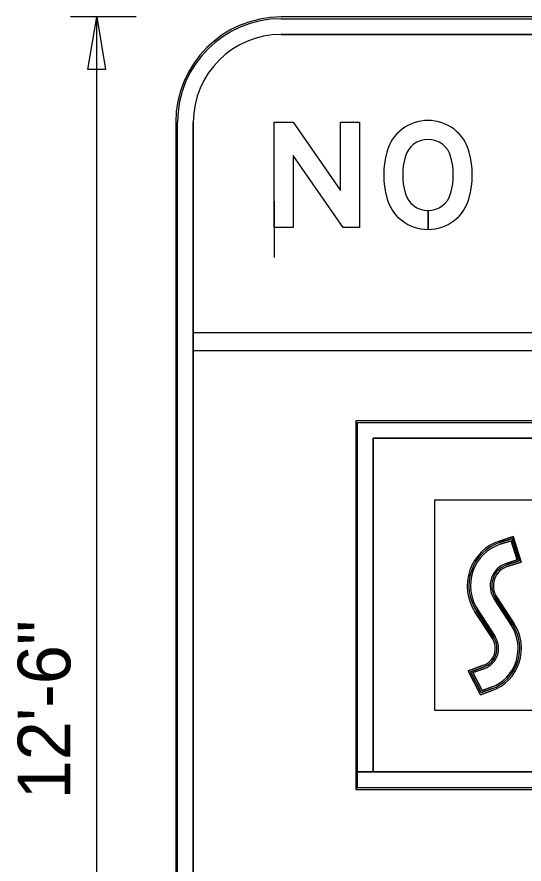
# Model space of a CAD drawing. Extents: x 119523 to 121850, y -23542 to -19972.
# Drawn here: x 121310.8 to 121368.6, y -22914.3 to -22817.8 of the extents above; entities that cross this region are included whole.
import ezdxf

# ---------------------------------------------------------------- set-up
doc = ezdxf.new("R2010")
doc.units = 0
for name, color, linetype in [('GSBWFill', 7, 'Continuous'), ('GSColorFill', 7, 'Continuous'), ('GSDims', 7, 'Continuous'), ('GSOutline', 7, 'Continuous')]:
    doc.layers.add(name, color=color, linetype=linetype)

msp = doc.modelspace()

# ---------------------------------------------------------------- linework, layer by layer
at = {"layer": 'GSBWFill'}
for p, q in [((121442.9, -22817.831), (121340.9, -22817.831)), ((121340.9, -22819.831), (121442.9, -22819.831)), ((121328.9, -22829.831), (121328.9, -22955.831)), ((121330.9, -22955.831), (121330.9, -22829.831)), ((121357.64, -22839.881), (121357.64, -22842.041)), ((121357.641, -22842.041), (121357.641, -22839.881)), ((121452.9, -22853.831), (121330.9, -22853.831)), ((121330.9, -22853.831), (121330.9, -22855.831)), ((121330.9, -22855.831), (121452.9, -22855.831)), ((121434.4, -22863.831), (121349.4, -22863.831)), ((121349.4, -22863.831), (121349.4, -22903.811)), ((121351.4, -22903.811), (121351.4, -22865.831)), ((121351.4, -22865.831), (121432.4, -22865.831)), ((121358.409, -22872.83), (121425.409, -22872.83)), ((121358.409, -22896.83), (121358.409, -22872.83)), ((121425.409, -22896.83), (121358.409, -22896.83)), ((121349.4, -22903.811), (121351.4, -22903.811)), ((121432.4, -22903.831), (121349.4, -22903.831)), ((121349.4, -22903.831), (121349.4, -22905.831)), ((121349.4, -22905.831), (121434.4, -22905.831))]:
    msp.add_line(p, q, dxfattribs=at)
msp.add_lwpolyline([(121349.84, -22829.831), (121349.84, -22841.831), (121347.98, -22841.831), (121342.28, -22833.611), (121342.28, -22841.831), (121340.12, -22841.831), (121340.12, -22829.831), (121342.288, -22829.831), (121347.68, -22837.607), (121347.68, -22829.831)], close=True, dxfattribs=at)
for points in [[(121366.662, -22880.44), (121368.254, -22879.926), (121367.357, -22877.021), (121365.765, -22877.535)], [(121365.821, -22877.714), (121367.236, -22877.257), (121368.02, -22879.799), (121366.606, -22880.256)], [(121365.314, -22884.012), (121367.294, -22887.051)], [(121367.449, -22886.948), (121365.469, -22883.909)], [(121362.991, -22885.599), (121364.971, -22888.638)], [(121365.126, -22888.53), (121363.146, -22885.49)], [(121363.972, -22891.681), (121362.204, -22892.311), (121363.623, -22895.032), (121364.951, -22894.559)], [(121364.889, -22894.376), (121363.712, -22894.795), (121362.471, -22892.415), (121364.033, -22891.859)]]:
    msp.add_lwpolyline(points, dxfattribs=at)
for radius in [12, 10]:
    msp.add_arc((121340.9, -22829.831), radius, 90, 180, dxfattribs=at)
for centre, major_axis, ratio, start_param, end_param in [((121357.64, -22834.484), (0, 4.863), 0.999996, 4.973521, 7.592849), ((121357.64, -22834.484), (0, 2.703), 0.999996, 4.973521, 7.592849), ((121362.68, -22835.831), (0, 10.08), 0.999996, 1.309664, 1.831929), ((121352.6, -22835.831), (0, 10.08), 0.999996, 4.451257, 4.973521), ((121362.68, -22835.831), (0, 7.92), 0.999996, 1.309664, 1.831929), ((121352.6, -22835.831), (0, 7.92), 0.999996, 4.451257, 4.973521), ((121357.64, -22837.177), (0, 4.863), 0.999996, 1.831929, 3.141593), ((121357.64, -22837.177), (0, 2.703), 0.999996, 1.831929, 3.141593), ((121357.64, -22837.177), (0, 2.703), 0.999996, 3.141815, 4.451257), ((121357.64, -22837.177), (0, 4.863), 0.999996, 3.141716, 4.451257), ((121367.339, -22882.633), (0, 5.346), 0.977477, 0.305879, 2.158799), ((121367.339, -22882.63), (0, 5.156), 0.977477, 0.305879, 2.158799), ((121367.339, -22882.63), (0, 2.49), 0.977477, 0.305879, 2.158799), ((121367.339, -22882.633), (0, 2.299), 0.977477, 0.305879, 2.158799), ((121363.32, -22889.761), (0, -4.886), 0.977477, 0.334737, 2.158799), ((121363.32, -22889.764), (0, -5.077), 0.977477, 0.334737, 2.158799), ((121363.32, -22889.764), (0, -2.03), 0.977477, 0.334742, 2.158799), ((121363.32, -22889.761), (0, -2.22), 0.977477, 0.334742, 2.158799)]:
    msp.add_ellipse(centre, major_axis=major_axis, ratio=ratio, start_param=start_param, end_param=end_param, dxfattribs=at)
at = {"layer": 'GSColorFill'}
for p, q in [((121442.9, -22817.831), (121340.9, -22817.831)), ((121442.9, -22817.831), (121340.9, -22817.831)), ((121442.9, -22817.831), (121340.9, -22817.831)), ((121340.9, -22818.031), (121442.9, -22818.031)), ((121340.9, -22819.831), (121442.9, -22819.831)), ((121328.9, -22829.831), (121328.9, -22955.831)), ((121328.9, -22829.831), (121328.9, -22955.831)), ((121328.9, -22829.831), (121328.9, -22955.831)), ((121329.1, -22955.831), (121329.1, -22829.831)), ((121330.9, -22955.831), (121330.9, -22829.831)), ((121357.64, -22839.881), (121357.64, -22842.041)), ((121357.641, -22842.041), (121357.641, -22839.881)), ((121452.9, -22853.831), (121330.9, -22853.831)), ((121330.9, -22853.831), (121330.9, -22855.831)), ((121330.9, -22855.831), (121452.9, -22855.831)), ((121434.4, -22863.831), (121349.4, -22863.831)), ((121349.4, -22863.831), (121349.4, -22905.831)), ((121434.4, -22863.831), (121349.4, -22863.831)), ((121349.4, -22863.831), (121349.4, -22903.811)), ((121434.4, -22863.831), (121349.4, -22863.831)), ((121349.4, -22863.831), (121349.4, -22905.629)), ((121349.6, -22905.629), (121349.6, -22864.031)), ((121349.6, -22864.031), (121434.2, -22864.031)), ((121351.4, -22903.811), (121351.4, -22865.831)), ((121351.4, -22865.831), (121432.4, -22865.831)), ((121349.4, -22903.811), (121351.4, -22903.811)), ((121432.4, -22903.831), (121349.4, -22903.831)), ((121349.4, -22903.831), (121349.4, -22905.831)), ((121349.4, -22905.629), (121349.6, -22905.629)), ((121434.2, -22905.631), (121349.4, -22905.631)), ((121349.4, -22905.631), (121349.4, -22905.831)), ((121349.4, -22905.831), (121434.4, -22905.831)), ((121349.4, -22905.831), (121434.4, -22905.831)), ((121349.4, -22905.831), (121434.4, -22905.831))]:
    msp.add_line(p, q, dxfattribs=at)
for points in [[(121349.84, -22829.831), (121349.84, -22841.831), (121347.98, -22841.831), (121342.28, -22833.611), (121342.28, -22841.831), (121340.12, -22841.831), (121340.12, -22829.831), (121342.288, -22829.831), (121347.68, -22837.607), (121347.68, -22829.831)], [(121358.409, -22872.83), (121425.409, -22872.83), (121425.409, -22896.83), (121358.409, -22896.83)]]:
    msp.add_lwpolyline(points, close=True, dxfattribs=at)
for points in [[(121366.662, -22880.44), (121368.254, -22879.926), (121367.357, -22877.021), (121365.765, -22877.535)], [(121366.606, -22880.256), (121368.02, -22879.799), (121367.236, -22877.257), (121365.821, -22877.714)], [(121366.55, -22880.072), (121367.787, -22879.672), (121367.114, -22877.493), (121365.877, -22877.893)], [(121367.14, -22887.154), (121365.159, -22884.114)], [(121367.294, -22887.051), (121365.314, -22884.012)], [(121367.449, -22886.948), (121365.469, -22883.909)], [(121362.991, -22885.599), (121364.971, -22888.638)], [(121363.146, -22885.49), (121365.126, -22888.53)], [(121363.3, -22885.382), (121365.281, -22888.421)], [(121363.972, -22891.681), (121362.204, -22892.311), (121363.623, -22895.032), (121364.951, -22894.559)], [(121364.033, -22891.859), (121362.471, -22892.415), (121363.712, -22894.795), (121364.889, -22894.376)], [(121364.095, -22892.036), (121362.737, -22892.519), (121363.801, -22894.559), (121364.828, -22894.194)]]:
    msp.add_lwpolyline(points, dxfattribs=at)
for radius in [12, 12, 12, 11.8, 10]:
    msp.add_arc((121340.9, -22829.831), radius, 90, 180, dxfattribs=at)
for centre, major_axis, ratio, start_param, end_param in [((121357.64, -22834.484), (0, 4.863), 0.999996, 4.973521, 7.592849), ((121357.64, -22834.484), (0, 2.703), 0.999996, 4.973521, 7.592849), ((121362.68, -22835.831), (0, 10.08), 0.999996, 1.309664, 1.831929), ((121352.6, -22835.831), (0, 10.08), 0.999996, 4.451257, 4.973521), ((121362.68, -22835.831), (0, 7.92), 0.999996, 1.309664, 1.831929), ((121352.6, -22835.831), (0, 7.92), 0.999996, 4.451257, 4.973521), ((121357.64, -22837.177), (0, 4.863), 0.999996, 1.831929, 3.141593), ((121357.64, -22837.177), (0, 2.703), 0.999996, 1.831929, 3.141593), ((121357.64, -22837.177), (0, 2.703), 0.999996, 3.141815, 4.451257), ((121357.64, -22837.177), (0, 4.863), 0.999996, 3.141716, 4.451257), ((121367.339, -22882.633), (0, 5.346), 0.977477, 0.305879, 2.158799), ((121367.339, -22882.63), (0, 5.156), 0.977477, 0.305879, 2.158799), ((121367.339, -22882.628), (0, 4.965), 0.977477, 0.305879, 2.158799), ((121367.339, -22882.628), (0, 2.68), 0.977477, 0.305879, 2.158799), ((121367.339, -22882.63), (0, 2.49), 0.977477, 0.305879, 2.158799), ((121367.339, -22882.633), (0, 2.299), 0.977477, 0.305879, 2.158799), ((121363.32, -22889.759), (0, -4.696), 0.977477, 0.334737, 2.158799), ((121363.32, -22889.761), (0, -4.886), 0.977477, 0.334737, 2.158799), ((121363.32, -22889.764), (0, -5.077), 0.977477, 0.334737, 2.158799), ((121363.32, -22889.764), (0, -2.03), 0.977477, 0.334742, 2.158799), ((121363.32, -22889.761), (0, -2.22), 0.977477, 0.334742, 2.158799), ((121363.32, -22889.759), (0, -2.411), 0.977477, 0.334742, 2.158799)]:
    msp.add_ellipse(centre, major_axis=major_axis, ratio=ratio, start_param=start_param, end_param=end_param, dxfattribs=at)
at = {"layer": 'GSDims'}
for p, q in [((121324.4, -22817.831), (121316.9, -22817.831)), ((121319.9, -22967.831), (121319.9, -22817.831)), ((121324.4, -22817.831), (121324.4, -22817.831)), ((121340.12, -22838.831), (121340.12, -22845.237))]:
    msp.add_line(p, q, dxfattribs=at)
msp.add_lwpolyline([(121319.9, -22817.831), (121320.9, -22823.831), (121318.9, -22823.831)], close=True, dxfattribs=at)
at = {"layer": 'GSOutline'}
for p, q in [((121442.9, -22817.831), (121340.9, -22817.831)), ((121442.9, -22819.831), (121340.9, -22819.831)), ((121328.9, -22829.831), (121328.9, -22955.831)), ((121330.9, -22829.831), (121330.9, -22955.831)), ((121452.9, -22853.831), (121330.9, -22853.831)), ((121330.9, -22853.831), (121330.9, -22855.831)), ((121330.9, -22855.831), (121452.9, -22855.831)), ((121434.4, -22863.831), (121349.4, -22863.831)), ((121349.4, -22863.831), (121349.4, -22905.831)), ((121432.4, -22865.831), (121351.4, -22865.831)), ((121351.4, -22865.831), (121351.4, -22903.831)), ((121365.765, -22877.535), (121367.357, -22877.021)), ((121367.357, -22877.021), (121368.254, -22879.926)), ((121365.821, -22877.714), (121367.236, -22877.257)), ((121365.877, -22877.893), (121367.114, -22877.493)), ((121367.114, -22877.493), (121367.787, -22879.672)), ((121367.236, -22877.257), (121368.02, -22879.799)), ((121367.787, -22879.672), (121366.55, -22880.072)), ((121368.02, -22879.799), (121366.606, -22880.256)), ((121368.254, -22879.926), (121366.662, -22880.44)), ((121365.159, -22884.114), (121367.14, -22887.154)), ((121365.314, -22884.012), (121367.294, -22887.051)), ((121365.469, -22883.909), (121367.449, -22886.948)), ((121364.971, -22888.638), (121362.991, -22885.599)), ((121365.126, -22888.53), (121363.146, -22885.49)), ((121365.281, -22888.421), (121363.3, -22885.382)), ((121362.204, -22892.311), (121363.972, -22891.681)), ((121363.623, -22895.032), (121362.204, -22892.311)), ((121362.471, -22892.415), (121364.033, -22891.859)), ((121363.712, -22894.795), (121362.471, -22892.415)), ((121362.737, -22892.519), (121364.095, -22892.036)), ((121363.801, -22894.559), (121362.737, -22892.519)), ((121364.889, -22894.376), (121363.712, -22894.795)), ((121364.828, -22894.194), (121363.801, -22894.559)), ((121364.951, -22894.559), (121363.623, -22895.032)), ((121351.4, -22903.831), (121432.4, -22903.831)), ((121349.4, -22905.831), (121434.4, -22905.831))]:
    msp.add_line(p, q, dxfattribs=at)
msp.add_lwpolyline([(121349.84, -22829.831), (121349.84, -22841.831), (121347.98, -22841.831), (121342.28, -22833.611), (121342.28, -22841.831), (121340.12, -22841.831), (121340.12, -22829.831), (121342.288, -22829.831), (121347.68, -22837.607), (121347.68, -22829.831)], close=True, dxfattribs=at)
for radius in [12, 10]:
    msp.add_arc((121340.9, -22829.831), radius, 90, 180, dxfattribs=at)
for centre, major_axis, ratio, start_param, end_param in [((121357.64, -22834.484), (0, 4.863), 0.999996, 4.973521, 7.592849), ((121357.64, -22834.484), (0, 2.703), 0.999996, 4.973521, 7.592849), ((121362.68, -22835.831), (0, 10.08), 0.999996, 1.309664, 1.831929), ((121352.6, -22835.831), (0, 10.08), 0.999996, 4.451257, 4.973521), ((121362.68, -22835.831), (0, 7.92), 0.999996, 1.309664, 1.831929), ((121352.6, -22835.831), (0, 7.92), 0.999996, 4.451257, 4.973521), ((121357.64, -22837.177), (0, 4.863), 0.999996, 1.831929, 4.451257), ((121357.64, -22837.177), (0, 2.703), 0.999996, 1.831929, 4.451257), ((121367.339, -22882.633), (0, 5.346), 0.977477, 0.305879, 2.158799), ((121367.339, -22882.63), (0, 5.156), 0.977477, 0.305879, 2.158799), ((121367.339, -22882.628), (0, 4.965), 0.977477, 0.305879, 2.158799), ((121367.339, -22882.628), (0, 2.68), 0.977477, 0.305879, 2.158799), ((121367.339, -22882.63), (0, 2.49), 0.977477, 0.305879, 2.158799), ((121367.339, -22882.633), (0, 2.299), 0.977477, 0.305879, 2.158799), ((121363.32, -22889.759), (0, -4.696), 0.977477, 0.334737, 2.158799), ((121363.32, -22889.761), (0, -4.886), 0.977477, 0.334737, 2.158799), ((121363.32, -22889.764), (0, -5.077), 0.977477, 0.334737, 2.158799), ((121363.32, -22889.764), (0, -2.03), 0.977477, 0.334742, 2.158799), ((121363.32, -22889.761), (0, -2.22), 0.977477, 0.334742, 2.158799), ((121363.32, -22889.759), (0, -2.411), 0.977477, 0.334742, 2.158799)]:
    msp.add_ellipse(centre, major_axis=major_axis, ratio=ratio, start_param=start_param, end_param=end_param, dxfattribs=at)

# ---------------------------------------------------------------- texts
at = {"layer": 'GSDims'}
msp.add_text('12\'-6"', height=6, rotation=90, dxfattribs=at).set_placement((121316.9, -22906.973))

doc.saveas('drawing.dxf')
